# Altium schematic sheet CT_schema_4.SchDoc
size 322 x 229 mm
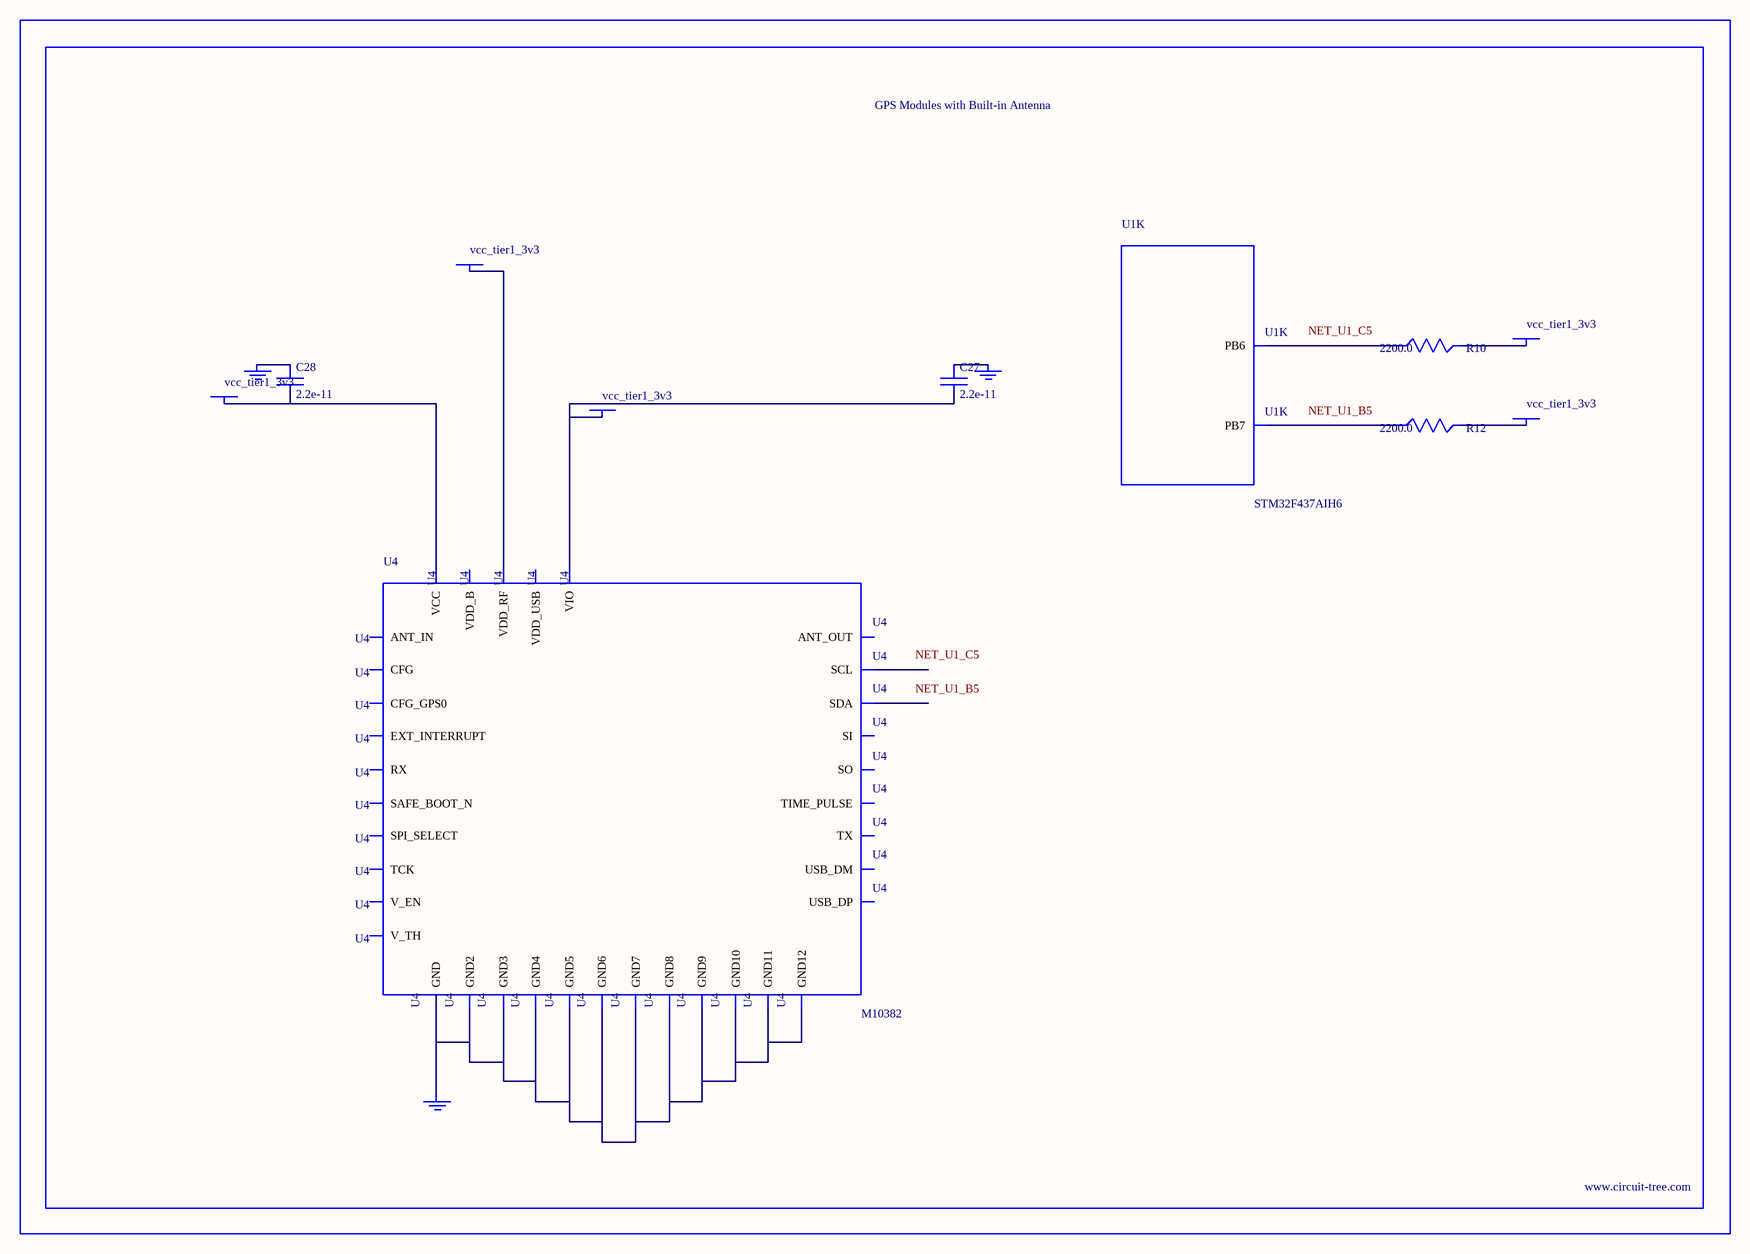
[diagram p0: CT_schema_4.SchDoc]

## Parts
BORDER3  (no value)
C27  2.2e-11  [C0402]
C28  2.2e-11  [C0402]
GND_INSTANCE_3_0  (no value)
GND_INSTANCE_3_1  (no value)
GND_INSTANCE_3_2  (no value)
POWER_INSTANCE_3_0  vcc_tier1_3v3
POWER_INSTANCE_3_1  vcc_tier1_3v3
POWER_INSTANCE_3_2  vcc_tier1_3v3
POWER_INSTANCE_3_3  vcc_tier1_3v3
POWER_INSTANCE_3_4  vcc_tier1_3v3
R10  2200.0  [R0603]
R12  2200.0  [R0603]
U1  STM32F437AIH6  [UFBGA169]  (part K of 12)
U4  M10382  [M10382]

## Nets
NetC27_1: C27.1 GND_INSTANCE_3_0.0(GND)
NetC27_2: C27.2 POWER_INSTANCE_3_0.0(PWR) U4.5(VIO)
NetC28_1: C28.1 GND_INSTANCE_3_1.0(GND)
NetC28_2: C28.2 POWER_INSTANCE_3_2.0(PWR) U4.27(VCC)
NetGND_INSTANCE_3_2_0: GND_INSTANCE_3_2.0(GND) U4.2(GND) U4.4(GND2) U4.14(GND3) U4.17(GND4) U4.21(GND5) U4.24(GND6) U4.26(GND7) U4.28(GND8) U4.33(GND9) U4.34(GND10) U4.35(GND11) U4.36(GND12)
NetPOWER_INSTANCE_3_1_0: POWER_INSTANCE_3_1.0(PWR) U4.25(VDD_RF)
NetPOWER_INSTANCE_3_3_0: POWER_INSTANCE_3_3.0(PWR) R10.2
NetPOWER_INSTANCE_3_4_0: POWER_INSTANCE_3_4.0(PWR) R12.2
NetR10_1: R10.1 U1.C5(PB6)
NetR12_1: R12.1 U1.B5(PB7)

Not connected (* = marked no-connect by the designer): U4 1(ANT_IN) 3(ANT_OUT) 6(USB_DP) 7(USB_DM) 8(SO) 9(CFG_GPS0) 10(SPI_SELECT) 11(TX) 12(V_TH) 13(RX) 15(VDD_B) 16(SI) 18(SDA) 19(SCL) 20(SAFE_BOOT_N) 22(TCK) 23(TIME_PULSE) 29(EXT_INTERRUPT) 30(V_EN) 31(CFG) 32(VDD_USB)

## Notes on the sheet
- Labels drawn without touching a wire or pin: NET_U1_B5, NET_U1_C5

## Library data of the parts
BORDER3 = BORDER_PAGE3
C27 C28 = C0402C220K3RAC
GND_INSTANCE_3_0-GND_INSTANCE_3_2 = GND
POWER_INSTANCE_3_0-POWER_INSTANCE_3_4 = PWR
R10 R12 = RC0603JR-072K2L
